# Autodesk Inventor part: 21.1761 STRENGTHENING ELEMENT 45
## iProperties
Created: 2007-04
Part Number: 21.1761 STRENGTHENING ELEMENT 45
Material: Aluminum-6061
Document SubType Name: Modeling
Designer: Andy Moles
Density: 2.71 g/cm^3
Mass: 687.214 g
Surface Area: 1626.34 cm^2
Volume: 253.585 cm^3
Author: Andy Moles
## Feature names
1. Extrusion1
2. Extrusion2
3. Extrusion3
4. Extrusion4
5. Mirror1
